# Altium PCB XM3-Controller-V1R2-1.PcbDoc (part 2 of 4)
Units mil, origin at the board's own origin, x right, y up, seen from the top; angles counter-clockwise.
Board outline 10629.92 x 4173.11 mil, 6 copper layers (TOP, GND1, LAYER3, PWR, GND2, BOTTOM), stack 62 mil thick; 362 components, 276 nets, 1145 pads, 503 vias.
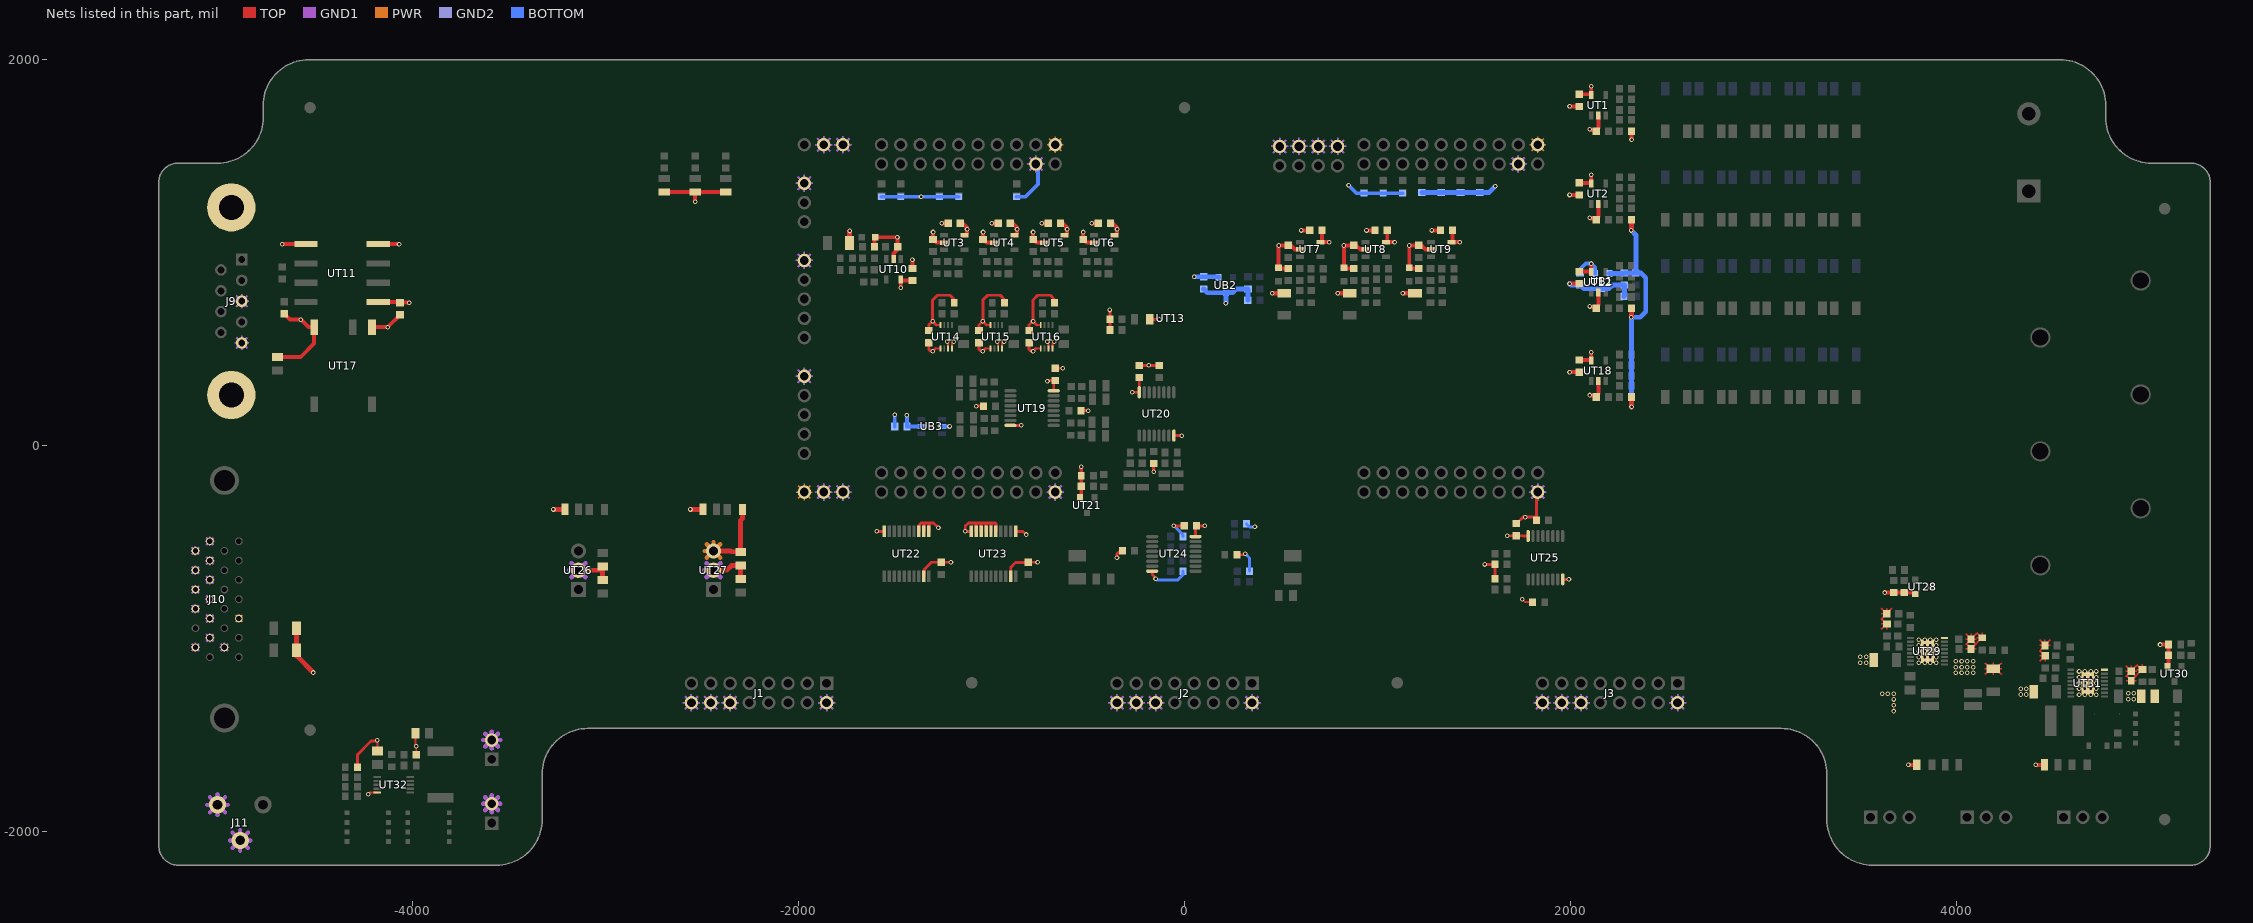
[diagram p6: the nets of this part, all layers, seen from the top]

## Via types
v1: diameter 24, hole 13, TOP to BOTTOM, 503 vias

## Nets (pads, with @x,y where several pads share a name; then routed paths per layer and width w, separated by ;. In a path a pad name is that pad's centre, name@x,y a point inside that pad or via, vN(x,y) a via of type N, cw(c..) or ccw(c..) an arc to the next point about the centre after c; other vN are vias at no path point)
0: CB1.2 CB2.2 CB3.2 CB4.2 CB5.2 CB6.2 CB7.2 CB8.2 CB9.2 CB10.2 CB11.2 CB12.2 CB13.2 CB14.2 CB15.2 CB16.2 CB17.2 CB18.2 CB19.2 CB20.2 CB21.2 CB22.2 CB23.2 CT1.2 CT3.1 CT4.2 CT6.1 CT7.2 CT8.2 CT9.2 CT10.2 CT11.2 CT12.2 CT13.2 CT14.2 CT15.1 CT16.1 CT17.1 CT18.1 CT19.2 CT20.2 CT21.2 CT22.2 CT30.2 CT31.2 CT32.2 CT33.2 CT35.2 CT38.1 CT39.2 CT43.1 CT44.2 CT45.2 CT46.2 CT48.2 CT49.2 CT50.2 CT54.1 CT59.2 CT60.2 CT61.2 CT62.2 CT63.2 CT64.2 CT65.2 CT66.2 CT67.2 CT68.2 CT69.2 CT70.2 CT71.2 CT72.2 CT73.1 CT74.1 CT75.2 CT76.2 CT77.2 CT78.2 CT79.1 CT80.1 CT81.2 CT83.2 CT84.2 CT85.2 CT86.2 CT87.2 CT88.2 DT1.2 DT2.2 DT3.2 DT4.2 DT5.2 DT8.1 DT12.2 J1.2 J1.12 J1.14 J1.16 J2.2 J2.12 J2.14 J2.16 J3.2 J3.12 J3.14 J3.16 J10.3 J10.4 J10.5 J10.9 J10.11 J10.13 J10.15 J10.17 J10.19 J10.21 J10.23 J10.25 J11.2 J11.3 J12.2 J13.2 RT4.1 RT36.2 RT37.1 RT51.1 RT53.1 RT55.1 RT72.2 RT73.2 RT74.2 RT82.1 RT89.2 RT101.2 RT107.2 RT111.1 RT114.1 RT117.2 RT123.2 RT124.2 RT126.1 RT131.2 RT134.1 RT137.1 RT140.2 UB1.3 UB2.3 UB3.2 UT1.2 UT2.2 UT3.2 UT4.2 UT5.2 UT6.2 UT7.2 UT8.2 UT9.2 UT10.2 UT11.4 UT12.2 UT13.20 UT13.22 UT13.60 UT13.62 UT13.82 UT13.84 UT13.86 UT13.88 UT13.93 UT13.98 UT13.101 UT13.103 UT13.104 UT13.106 UT13.107 UT14.1 UT14.4 UT15.1 UT15.4 UT16.1 UT16.4 UT17.1 UT18.2 UT19.8 UT20.8 UT21.2 UT22.1 UT22.2 UT22.3 UT22.10 UT22.19 UT23.1 UT23.5 UT23.6 UT23.7 UT23.8 UT23.9 UT23.10 UT23.19 UT24.8 UT25.8 UT26.2 UT27.2 UT28.2 UT29.16 UT29.17 UT30.2 UT31.16 UT31.17 UT32.5 | length 39476.6
  TOP w7: 3610.78,-870 CT71.2@3638.5,-870 ; 3611.23,-898.71 CT71.2@3638.5,-870 ; 3611.23,-841.29 CT71.2@3638.5,-870 ; 3611.29,-950.77 CT73.1@3640,-923.5 ; 3611.29,-923.5 CT73.1@3640,-923.5 ; 3611.29,-896.23 CT73.1@3640,-923.5 ; 3638.5,-841.29 CT71.2@3638.5,-870 ; 3640,-951.22 CT73.1@3640,-923.5 ; 3665.77,-841.29 CT71.2@3638.5,-870 ; 4047.78,-1003 CT74.1@4075.5,-1003 ; 4048.23,-1031.71 CT74.1@4075.5,-1003 ; 4048.23,-974.29 CT74.1@4075.5,-1003 ; 4048.76,-1053 RT126.1@4075.5,-1053 ; 4049.66,-1024.29 RT126.1@4075.5,-1053 ; 4075.5,-974.29 CT74.1@4075.5,-1003 ; 4101.34,-1024.29 RT126.1@4075.5,-1053 ; 4102.24,-1053 RT126.1@4075.5,-1053 ; 4102.77,-1031.71 CT74.1@4075.5,-1003 ; 4102.77,-974.29 CT74.1@4075.5,-1003 ; 4103.22,-1003 CT74.1@4075.5,-1003 ; 4105.29,-1020.34 RT123.2@4134,-994.5 ; 4105.29,-994.5 RT123.2@4134,-994.5 ; 4105.29,-968.66 RT123.2@4134,-994.5 ; 4134,-967.76 RT123.2@4134,-994.5 ; 4145.54,-1184.35 CT81.2@4190,-1155.94 ; 4145.54,-1155.94 CT81.2@4190,-1155.94 ; 4145.54,-1127.53 CT81.2@4190,-1155.94 ; 4190,-1187.6 CT81.2@4190,-1155.94 ; 4190,-1124.28 CT81.2@4190,-1155.94 ; 4234.46,-1184.35 CT81.2@4190,-1155.94 ; 4234.46,-1155.94 CT81.2@4190,-1155.94 ; 4234.46,-1127.53 CT81.2@4190,-1155.94 ; 4430.78,-1035 CT75.2@4458.5,-1035 ; 4431.23,-1063.71 CT75.2@4458.5,-1035 ; 4431.23,-1006.29 CT75.2@4458.5,-1035 ; 4431.29,-1115.77 CT79.1@4460,-1088.5 ; 4431.29,-1088.5 CT79.1@4460,-1088.5 ; 4431.29,-1061.23 CT79.1@4460,-1088.5 ; 4458.5,-1006.29 CT75.2@4458.5,-1035 ; 4460,-1116.22 CT79.1@4460,-1088.5 ; 4485.77,-1006.29 CT75.2@4458.5,-1035 ; 4486.22,-1035 CT75.2@4458.5,-1035 ; 4877.78,-1168 CT80.1@4905.5,-1168 ; 4878.23,-1196.71 CT80.1@4905.5,-1168 ; 4878.23,-1139.29 CT80.1@4905.5,-1168 ; 4878.76,-1218 RT134.1@4905.5,-1218 ; 4879.66,-1189.29 RT134.1@4905.5,-1218 ; 4905.5,-1139.29 CT80.1@4905.5,-1168 ; 4931.34,-1189.29 RT134.1@4905.5,-1218 ; 4932.24,-1218 RT134.1@4905.5,-1218 ; 4932.77,-1196.71 CT80.1@4905.5,-1168 ; 4932.77,-1139.29 CT80.1@4905.5,-1168 ; 4933.22,-1168 CT80.1@4905.5,-1168 ; 4935.29,-1185.34 RT131.2@4964,-1159.5 ; 4935.29,-1159.5 RT131.2@4964,-1159.5 ; 4935.29,-1133.66 RT131.2@4964,-1159.5 ; 4964,-1132.76 RT131.2@4964,-1159.5
  TOP w10: v1(-4230,-1805) -4221.67,-1796.67 UT32.5@-4182.5,-1796.67 ; CT88.2@-4182.5,-1581.24 v1(-4182.5,-1526.67) ; CT86.2@-3985.43,-1490 -3985.43,-1552.24 v1(-3981,-1556.67) CT87.2@-3981,-1601.67 ; -1291,504 UT14.1@-1265,504 ; UT14.4@-1205,504 -1205,530 v1(-1195,540) ; -1031,504 UT15.1@-1005,504 ; UT15.4@-945,504 -945,530 v1(-935,540) ; -771,504 UT16.1@-745,504 ; UT16.4@-685,504 -685,530 v1(-675,540)
  TOP w15: RT140.2@-4286,-1666.67 -4286,-1601 -4215,-1530 -4185.83,-1530 v1(-4182.5,-1526.67) ; v1(-1593.86,-443.86) UT22.10@-1555.16,-443.86 ; UT22.3@-1376.02,-443.86 -1376.02,-410.55 -1365.3,-399.83 -1350,-399.83 ; UT22.19@-1350.43,-676.14 -1350.43,-642.83 -1311.1,-603.5 CT65.2@-1260,-603.5 v1(-1210,-603.5) ; UT22.2@-1350.43,-443.86 -1350.43,-400.26 -1350,-399.83 ; CT44.2@-1325,533.5 -1325,500 -1315,490 v1(-1305,490) -1291,504 ; UT22.1@-1324.84,-443.86 -1324.84,-399.99 -1325,-399.83 ; v1(-1275,-425) -1300.17,-399.83 -1325,-399.83 ; UT23.10@-1105.16,-443.86 v1(-1136.14,-443.86) -1136.14,-415.94 -1120.03,-399.83 -1080,-399.83 ; UT23.9@-1079.57,-443.86 -1079.57,-400.26 -1080,-399.83 ; CT45.2@-1065,533.5 -1065,500 -1055,490 v1(-1045,490) -1031,504 ; UT23.8@-1053.98,-443.86 -1053.98,-400.85 -1055,-399.83 ; UT23.7@-1028.39,-443.86 -1028.39,-401.44 -1030,-399.83 ; UT23.6@-1002.8,-443.86 -1002.8,-402.03 -1005,-399.83 ; UT23.5@-977.2,-443.86 -977.2,-402.63 -980,-399.83 -1005,-399.83 ; UT19.8@-902.2,105.43 v1(-845,105.43) ; UT23.19@-900.43,-676.14 -900.43,-630.43 -875,-605 -811.5,-605 CT66.2@-810,-603.5 v1(-761.5,-603.5) ; UT23.1@-874.84,-443.86 -836.14,-443.86 v1(-820,-460) ; CT46.2@-805,533.5 -805,500 -795,490 v1(-785,490) -771,504 ; CT50.2@-670,401.5 v1(-630,401.5) ; RT101.2@-535.5,182 v1(-498.78,182) ; CT43.1@-386.5,600 RT82.1@-386.5,655 v1(-386.5,703.5) ; CT49.2@-235,416.5 -185.16,416.5 v1(-185,416.34) RT89.2@-130,416.34 ; UT24.8@-167.2,-649.57 -167.2,-667.8 -150,-685 v1(-150,-690) ; UT20.8@-55.43,52.8 v1(-15,52.8) ; v1(-55,-415) CT60.2@-1.5,-415 ; RT114.1@271.5,-565 310,-565 v1(315,-560) ; v1(1555,-615) CT64.2@1608.5,-615 CT67.2@1608.5,-690 ; CT61.2@1720,-403.5 1753.5,-370 v1(1765,-370) 1810.47,-370 RT111.1@1823.5,-383.03 ; RT111.1@1823.5,-385 RT111.1@1823.5,-383.03 ; UT13.20@1830,-240 1823.5,-246.5 RT111.1@1823.5,-383.03 ; UT25.8@1959.57,-692.2 v1(1992.2,-692.2) ; -1350,-399.83 -1325,-399.83 ; -1080,-399.83 -1055,-399.83 ; -1055,-399.83 -1030,-399.83 ; -1030,-399.83 -1005,-399.83
  TOP w20: UT17.1@-4210,615 v1(-4128.5,615) CT39.2@-4065,678.5 ; UT11.4@-4177.5,1045 v1(-4070,1045) ; DT1.2@-2695,1315 DT2.2@-2535.94,1315 ; v1(-2535.94,1265) DT2.2@-2535.94,1315 ; DT3.2@-2376.88,1315 DT2.2@-2535.94,1315 ; RT37.1@-1606,1030.64 -1606,1077.14 CT14.2@-1602.5,1080.64 v1(-1487.5,1080.64) -1487.5,1050.64 -1486.54,1049.68 -1486.54,1031.18 CT19.2@-1486,1030.64 -1486,1017.14 -1507.5,995.64 UT10.2@-1507.5,968.79 ; CT30.2@-1409.53,919.2 v1(-1409.53,963.61) ; v1(-1303.15,1107.4) CT15.1@-1303.15,1068.9 -1286.65,1052.4 UT3.2@-1246.3,1052.4 ; v1(-1258.15,1152.4) CT7.2@-1224.65,1152.4 ; v1(-1043.97,1107.4) CT16.1@-1043.97,1068.9 -1027.47,1052.4 UT4.2@-987.12,1052.4 ; v1(-998.97,1152.4) CT8.2@-965.47,1152.4 ; v1(-784.79,1107.4) CT17.1@-784.79,1068.9 -768.29,1052.4 UT5.2@-727.94,1052.4 ; v1(-739.79,1152.4) CT9.2@-706.29,1152.4 ; UT21.2@-541.29,-267.84 -534.79,-261.34 CT59.2@-534.79,-210.85 RT107.2@-534.79,-155.84 v1(-534.79,-109.34) ; v1(-525.61,1107.4) CT18.1@-525.61,1068.9 -509.11,1052.4 UT6.2@-468.76,1052.4 ; v1(-480.61,1152.4) CT10.2@-447.11,1152.4 ; RT51.1@537.5,919.19 491,919.19 CT31.2@487.5,922.69 v1(487.5,1037.69) 517.5,1037.69 518.46,1038.65 536.96,1038.65 CT20.2@537.5,1039.19 551,1039.19 572.5,1017.69 UT7.2@599.35,1017.69 ; v1(604.53,1115.66) CT11.2@648.94,1115.66 ; RT53.1@876.02,919.19 829.52,919.19 CT32.2@826.02,922.69 v1(826.02,1037.69) 856.02,1037.69 856.98,1038.65 875.48,1038.65 CT21.2@876.02,1039.19 889.52,1039.19 911.02,1017.69 UT8.2@937.87,1017.69 ; v1(943.05,1115.66) CT12.2@987.46,1115.66 ; RT55.1@1214.54,919.19 1168.04,919.19 CT33.2@1164.54,922.69 v1(1164.54,1037.69) 1194.54,1037.69 1195.5,1038.65 1214,1038.65 CT22.2@1214.54,1039.19 1228.04,1039.19 1249.54,1017.69 UT9.2@1276.39,1017.69 ; v1(1281.57,1115.66) CT13.2@1325.98,1115.66 ; v1(1995,381.32) CT48.2@2045,381.32 ; v1(1995,840.38) CT35.2@2045,840.38 ; v1(1995,1299.44) CT4.2@2045,1299.44 ; v1(1995,1758.5) CT1.2@2045,1758.5 ; v1(2100,262.82) 2103.5,259.32 2132,259.32 CT54.1@2133.5,257.82 ; v1(2100,721.88) 2103.5,718.38 2132,718.38 CT38.1@2133.5,716.88 ; v1(2100,1180.94) 2103.5,1177.44 2132,1177.44 CT6.1@2133.5,1175.94 ; v1(2100,1640) 2103.5,1636.5 2132,1636.5 CT3.1@2133.5,1635 ; CT54.1@2133.5,252.82 CT54.1@2133.5,257.82 ; CT38.1@2133.5,711.88 CT38.1@2133.5,716.88 ; CT6.1@2133.5,1170.94 CT6.1@2133.5,1175.94 ; CT3.1@2133.5,1630 CT3.1@2133.5,1635 ; UT18.2@2145,334.67 2145,269.32 CT54.1@2133.5,257.82 ; UT12.2@2145,793.73 2145,728.38 CT38.1@2133.5,716.88 ; UT2.2@2145,1252.79 2145,1187.44 CT6.1@2133.5,1175.94 ; UT1.2@2145,1711.85 2145,1646.5 CT3.1@2133.5,1635 ; v1(2316.5,1586.5) RT4.1@2316.5,1630 ; v1(3628.5,-760.5) RT117.2@3675,-760.5 CT69.2@3730.01,-760.5 3780.5,-760.5 UT28.2@3787,-767 ; v1(3751.53,-1653.47) RT137.1@3794.85,-1653.47 ; v1(4411.53,-1653.47) DT12.2@4456,-1653.47 ; v1(5055,-1030) RT124.2@5099.5,-1030 CT77.2@5099.5,-1085.01 5099.5,-1135.5 UT30.2@5093,-1142
  TOP w25: CT72.2@-4600.94,-945 CT76.2@-4600.94,-1060 -4600.94,-1089.06 v1(-4515,-1175) ; v1(-3270,-330) DT4.2@-3210,-330 ; UT26.2@-3140.47,-645 -3034.57,-645 CT63.2@-3015,-625.43 CT70.2@-3015,-694.57 ; v1(-2560,-330) DT5.2@-2495,-330 ; UT27.2@-2440.47,-645 -2371.63,-645 -2347.06,-620.43 CT62.2@-2300,-620.43 CT68.2@-2300,-689.57 ; RT36.2@-1735.41,1050.64 -1735.19,1050.86 v1(-1735.19,1113.14) ; v1(455,790) 517.28,790 RT72.2@517.5,789.78 ; v1(793.52,790) 855.8,790 RT73.2@856.02,789.78 ; v1(1132.04,790) 1194.32,790 RT74.2@1194.54,789.78
  GND1 w7: -5148.02,-1045 J10.3@-5125,-1045 ; -5148.02,-845 J10.11@-5125,-845 ; -5148.02,-745 J10.15@-5125,-745 ; -5148.02,-645 J10.19@-5125,-645 ; -5148.02,-545 J10.23@-5125,-545 ; -5143.28,-1063.28 J10.3@-5125,-1045 ; -5143.28,-1026.72 J10.3@-5125,-1045 ; -5143.28,-863.28 J10.11@-5125,-845 ; -5143.28,-826.72 J10.11@-5125,-845 ; -5143.28,-763.28 J10.15@-5125,-745 ; -5143.28,-726.72 J10.15@-5125,-745 ; -5143.28,-663.28 J10.19@-5125,-645 ; -5143.28,-626.72 J10.19@-5125,-645 ; -5143.28,-563.28 J10.23@-5125,-545 ; -5143.28,-526.72 J10.23@-5125,-545 ; -5125,-1068.02 J10.3@-5125,-1045 ; -5125,-1021.98 J10.3@-5125,-1045 ; -5125,-868.02 J10.11@-5125,-845 ; -5125,-821.98 J10.11@-5125,-845 ; -5125,-768.02 J10.15@-5125,-745 ; -5125,-721.98 J10.15@-5125,-745 ; -5125,-668.02 J10.19@-5125,-645 ; -5125,-621.98 J10.19@-5125,-645 ; -5125,-568.02 J10.23@-5125,-545 ; -5125,-521.98 J10.23@-5125,-545 ; -5106.72,-1063.28 J10.3@-5125,-1045 ; -5106.72,-1026.72 J10.3@-5125,-1045 ; -5106.72,-863.28 J10.11@-5125,-845 ; -5106.72,-826.72 J10.11@-5125,-845 ; -5106.72,-763.28 J10.15@-5125,-745 ; -5106.72,-726.72 J10.15@-5125,-745 ; -5106.72,-663.28 J10.19@-5125,-645 ; -5106.72,-626.72 J10.19@-5125,-645 ; -5106.72,-563.28 J10.23@-5125,-545 ; -5106.72,-526.72 J10.23@-5125,-545 ; -5101.98,-1045 J10.3@-5125,-1045 ; -5101.98,-845 J10.11@-5125,-845 ; -5101.98,-745 J10.15@-5125,-745 ; -5101.98,-645 J10.19@-5125,-645 ; -5101.98,-545 J10.23@-5125,-545 ; -5073.02,-995 J10.5@-5050,-995 ; -5073.02,-895 J10.9@-5050,-895 ; -5073.02,-795 J10.13@-5050,-795 ; -5073.02,-695 J10.17@-5050,-695 ; -5073.02,-595 J10.21@-5050,-595 ; -5073.02,-495 J10.25@-5050,-495 ; -5068.28,-1013.28 J10.5@-5050,-995 ; -5068.28,-976.72 J10.5@-5050,-995 ; -5068.28,-913.28 J10.9@-5050,-895 ; -5068.28,-876.72 J10.9@-5050,-895 ; -5068.28,-813.28 J10.13@-5050,-795 ; -5068.28,-776.72 J10.13@-5050,-795 ; -5068.28,-713.28 J10.17@-5050,-695 ; -5068.28,-676.72 J10.17@-5050,-695 ; -5068.28,-613.28 J10.21@-5050,-595 ; -5068.28,-576.72 J10.21@-5050,-595 ; -5068.28,-513.28 J10.25@-5050,-495 ; -5068.28,-476.72 J10.25@-5050,-495 ; -5050,-1018.02 J10.5@-5050,-995 ; -5050,-971.98 J10.5@-5050,-995 ; -5050,-918.02 J10.9@-5050,-895 ; -5050,-871.98 J10.9@-5050,-895 ; -5050,-818.02 J10.13@-5050,-795 ; -5050,-771.98 J10.13@-5050,-795 ; -5050,-718.02 J10.17@-5050,-695 ; -5050,-671.98 J10.17@-5050,-695 ; -5050,-618.02 J10.21@-5050,-595 ; -5050,-571.98 J10.21@-5050,-595 ; -5050,-518.02 J10.25@-5050,-495 ; -5050,-471.98 J10.25@-5050,-495 ; -5031.72,-1013.28 J10.5@-5050,-995 ; -5031.72,-976.72 J10.5@-5050,-995 ; -5031.72,-913.28 J10.9@-5050,-895 ; -5031.72,-876.72 J10.9@-5050,-895 ; -5031.72,-813.28 J10.13@-5050,-795 ; -5031.72,-776.72 J10.13@-5050,-795 ; -5031.72,-713.28 J10.17@-5050,-695 ; -5031.72,-676.72 J10.17@-5050,-695 ; -5031.72,-613.28 J10.21@-5050,-595 ; -5031.72,-576.72 J10.21@-5050,-595 ; -5031.72,-513.28 J10.25@-5050,-495 ; -5031.72,-476.72 J10.25@-5050,-495 ; -5026.98,-995 J10.5@-5050,-995 ; -5026.98,-895 J10.9@-5050,-895 ; -5026.98,-795 J10.13@-5050,-795 ; -5026.98,-695 J10.17@-5050,-695 ; -5026.98,-595 J10.21@-5050,-595 ; -5026.98,-495 J10.25@-5050,-495 ; -4998.02,-1045 J10.4@-4975,-1045 ; -4993.28,-1063.28 J10.4@-4975,-1045 ; -4993.28,-1026.72 J10.4@-4975,-1045 ; -4975,-1068.02 J10.4@-4975,-1045 ; -4975,-1021.98 J10.4@-4975,-1045 ; -4956.72,-1063.28 J10.4@-4975,-1045 ; -4956.72,-1026.72 J10.4@-4975,-1045 ; -4951.98,-1045 J10.4@-4975,-1045 ; -2598.74,-1331.36 J1.16@-2554.72,-1331.36 ; -2587.85,-1364.49 J1.16@-2554.72,-1331.36 ; -2587.85,-1298.23 J1.16@-2554.72,-1331.36 ; -2554.72,-1375.38 J1.16@-2554.72,-1331.36 ; -2554.72,-1287.34 J1.16@-2554.72,-1331.36 ; -2521.59,-1364.49 J1.16@-2554.72,-1331.36 ; -2521.59,-1298.23 J1.16@-2554.72,-1331.36 ; -2510.7,-1331.36 J1.16@-2554.72,-1331.36 ; -2498.74,-1331.36 J1.14@-2454.72,-1331.36 ; -2487.85,-1364.49 J1.14@-2454.72,-1331.36 ; -2487.85,-1298.23 J1.14@-2454.72,-1331.36 ; -2454.72,-1375.38 J1.14@-2454.72,-1331.36 ; -2454.72,-1287.34 J1.14@-2454.72,-1331.36 ; -2421.59,-1364.49 J1.14@-2454.72,-1331.36 ; -2421.59,-1298.23 J1.14@-2454.72,-1331.36 ; -2410.7,-1331.36 J1.14@-2454.72,-1331.36 ; -2398.74,-1331.36 J1.12@-2354.72,-1331.36 ; -2387.85,-1364.49 J1.12@-2354.72,-1331.36 ; -2387.85,-1298.23 J1.12@-2354.72,-1331.36 ; -2354.72,-1375.38 J1.12@-2354.72,-1331.36 ; -2354.72,-1287.34 J1.12@-2354.72,-1331.36 ; -2321.59,-1364.49 J1.12@-2354.72,-1331.36 ; -2321.59,-1298.23 J1.12@-2354.72,-1331.36 ; -2310.7,-1331.36 J1.12@-2354.72,-1331.36 ; -2014.02,360 UT13.93@-1970,360 ; -2014.02,960 UT13.98@-1970,960 ; -2014.02,1360 UT13.101@-1970,1360 ; -2003.13,326.87 UT13.93@-1970,360 ; -2003.13,393.13 UT13.93@-1970,360 ; -2003.13,926.87 UT13.98@-1970,960 ; -2003.13,993.13 UT13.98@-1970,960 ; -2003.13,1326.87 UT13.101@-1970,1360 ; -2003.13,1393.13 UT13.101@-1970,1360 ; -1970,315.98 UT13.93@-1970,360 ; -1970,404.02 UT13.93@-1970,360 ; -1970,915.98 UT13.98@-1970,960 ; -1970,1004.02 UT13.98@-1970,960 ; -1970,1315.98 UT13.101@-1970,1360 ; -1970,1404.02 UT13.101@-1970,1360 ; -1936.87,326.87 UT13.93@-1970,360 ; -1936.87,393.13 UT13.93@-1970,360 ; -1936.87,926.87 UT13.98@-1970,960 ; -1936.87,993.13 UT13.98@-1970,960 ; -1936.87,1326.87 UT13.101@-1970,1360 ; -1936.87,1393.13 UT13.101@-1970,1360 ; -1925.98,360 UT13.93@-1970,360 ; -1925.98,960 UT13.98@-1970,960 ; -1925.98,1360 UT13.101@-1970,1360 ; -1914.02,-240 UT13.103@-1870,-240 ; -1914.02,1560 UT13.106@-1870,1560 ; -1903.13,-273.13 UT13.103@-1870,-240 ; -1903.13,-206.87 UT13.103@-1870,-240 ; -1903.13,1526.87 UT13.106@-1870,1560 ; -1903.13,1593.13 UT13.106@-1870,1560 ; -1898.74,-1331.36 J1.2@-1854.72,-1331.36 ; -1887.85,-1364.49 J1.2@-1854.72,-1331.36 ; -1887.85,-1298.23 J1.2@-1854.72,-1331.36 ; -1870,-284.02 UT13.103@-1870,-240 ; -1870,-195.98 UT13.103@-1870,-240 ; -1870,1515.98 UT13.106@-1870,1560 ; -1870,1604.02 UT13.106@-1870,1560 ; -1854.72,-1375.38 J1.2@-1854.72,-1331.36 ; -1854.72,-1287.34 J1.2@-1854.72,-1331.36 ; -1836.87,-273.13 UT13.103@-1870,-240 ; -1836.87,-206.87 UT13.103@-1870,-240 ; -1836.87,1526.87 UT13.106@-1870,1560 ; -1836.87,1593.13 UT13.106@-1870,1560 ; -1825.98,-240 UT13.103@-1870,-240 ; -1825.98,1560 UT13.106@-1870,1560 ; -1821.59,-1364.49 J1.2@-1854.72,-1331.36 ; -1821.59,-1298.23 J1.2@-1854.72,-1331.36 ; -1814.02,-240 UT13.104@-1770,-240 ; -1814.02,1560 UT13.107@-1770,1560 ; -1810.7,-1331.36 J1.2@-1854.72,-1331.36 ; -1803.13,-273.13 UT13.104@-1770,-240 ; -1803.13,-206.87 UT13.104@-1770,-240 ; -1803.13,1526.87 UT13.107@-1770,1560 ; -1803.13,1593.13 UT13.107@-1770,1560 ; -1770,-284.02 UT13.104@-1770,-240 ; -1770,-195.98 UT13.104@-1770,-240 ; -1770,1515.98 UT13.107@-1770,1560 ; -1770,1604.02 UT13.107@-1770,1560 ; -1736.87,-273.13 UT13.104@-1770,-240 ; -1736.87,-206.87 UT13.104@-1770,-240 ; -1736.87,1526.87 UT13.107@-1770,1560 ; -1736.87,1593.13 UT13.107@-1770,1560 ; -1725.98,-240 UT13.104@-1770,-240 ; -1725.98,1560 UT13.107@-1770,1560 ; -814.02,1460 UT13.62@-770,1460 ; -803.13,1426.87 UT13.62@-770,1460 ; -803.13,1493.13 UT13.62@-770,1460 ; -770,1415.98 UT13.62@-770,1460 ; -770,1504.02 UT13.62@-770,1460 ; -736.87,1426.87 UT13.62@-770,1460 ; -736.87,1493.13 UT13.62@-770,1460 ; -725.98,1460 UT13.62@-770,1460 ; -714.02,-240 UT13.60@-670,-240 ; -703.13,-273.13 UT13.60@-670,-240 ; -703.13,-206.87 UT13.60@-670,-240 ; -670,-284.02 UT13.60@-670,-240 ; -670,-195.98 UT13.60@-670,-240 ; -636.87,-273.13 UT13.60@-670,-240 ; -636.87,-206.87 UT13.60@-670,-240 ; -625.98,-240 UT13.60@-670,-240 ; -394.02,-1331.36 J2.16@-350,-1331.36 ; -383.13,-1364.49 J2.16@-350,-1331.36 ; -383.13,-1298.23 J2.16@-350,-1331.36 ; -350,-1375.38 J2.16@-350,-1331.36 ; -350,-1287.34 J2.16@-350,-1331.36 ; -316.87,-1364.49 J2.16@-350,-1331.36 ; -316.87,-1298.23 J2.16@-350,-1331.36 ; -305.98,-1331.36 J2.16@-350,-1331.36 ; -294.02,-1331.36 J2.14@-250,-1331.36 ; -283.13,-1364.49 J2.14@-250,-1331.36 ; -283.13,-1298.23 J2.14@-250,-1331.36 ; -250,-1375.38 J2.14@-250,-1331.36 ; -250,-1287.34 J2.14@-250,-1331.36 ; -216.87,-1364.49 J2.14@-250,-1331.36 ; -216.87,-1298.23 J2.14@-250,-1331.36 ; -205.98,-1331.36 J2.14@-250,-1331.36 ; -194.02,-1331.36 J2.12@-150,-1331.36 ; -183.13,-1364.49 J2.12@-150,-1331.36 ; -183.13,-1298.23 J2.12@-150,-1331.36 ; -150,-1375.38 J2.12@-150,-1331.36 ; -150,-1287.34 J2.12@-150,-1331.36 ; -116.87,-1364.49 J2.12@-150,-1331.36 ; -116.87,-1298.23 J2.12@-150,-1331.36 ; -105.98,-1331.36 J2.12@-150,-1331.36 ; 305.98,-1331.36 J2.2@350,-1331.36 ; 316.87,-1364.49 J2.2@350,-1331.36 ; 316.87,-1298.23 J2.2@350,-1331.36 ; 350,-1375.38 J2.2@350,-1331.36 ; 350,-1287.34 J2.2@350,-1331.36 ; 383.13,-1364.49 J2.2@350,-1331.36 ; 383.13,-1298.23 J2.2@350,-1331.36 ; 394.02,-1331.36 J2.2@350,-1331.36 ; 448.81,1550.79 UT13.88@492.83,1550.79 ; 459.7,1517.66 UT13.88@492.83,1550.79 ; 459.7,1583.92 UT13.88@492.83,1550.79 ; 492.83,1506.77 UT13.88@492.83,1550.79 ; 492.83,1594.81 UT13.88@492.83,1550.79 ; 525.96,1517.66 UT13.88@492.83,1550.79 ; 525.96,1583.92 UT13.88@492.83,1550.79 ; 536.85,1550.79 UT13.88@492.83,1550.79 ; 548.81,1550.79 UT13.86@592.83,1550.79 ; 559.7,1517.66 UT13.86@592.83,1550.79 ; 559.7,1583.92 UT13.86@592.83,1550.79 ; 592.83,1506.77 UT13.86@592.83,1550.79 ; 592.83,1594.81 UT13.86@592.83,1550.79 ; 625.96,1517.66 UT13.86@592.83,1550.79 ; 625.96,1583.92 UT13.86@592.83,1550.79 ; 636.85,1550.79 UT13.86@592.83,1550.79 ; 648.81,1550.79 UT13.84@692.83,1550.79 ; 659.7,1517.66 UT13.84@692.83,1550.79 ; 659.7,1583.92 UT13.84@692.83,1550.79 ; 692.83,1506.77 UT13.84@692.83,1550.79 ; 692.83,1594.81 UT13.84@692.83,1550.79 ; 725.96,1517.66 UT13.84@692.83,1550.79 ; 725.96,1583.92 UT13.84@692.83,1550.79 ; 736.85,1550.79 UT13.84@692.83,1550.79 ; 748.81,1550.79 UT13.82@792.83,1550.79 ; 759.7,1517.66 UT13.82@792.83,1550.79 ; 759.7,1583.92 UT13.82@792.83,1550.79 ; 792.83,1506.77 UT13.82@792.83,1550.79 ; 792.83,1594.81 UT13.82@792.83,1550.79 ; 825.96,1517.66 UT13.82@792.83,1550.79 ; 825.96,1583.92 UT13.82@792.83,1550.79 ; 836.85,1550.79 UT13.82@792.83,1550.79 ; 1685.98,1460 UT13.22@1730,1460 ; 1696.87,1426.87 UT13.22@1730,1460 ; 1696.87,1493.13 UT13.22@1730,1460 ; 1730,1415.98 UT13.22@1730,1460 ; 1730,1504.02 UT13.22@1730,1460 ; 1763.13,1426.87 UT13.22@1730,1460 ; 1763.13,1493.13 UT13.22@1730,1460 ; 1774.02,1460 UT13.22@1730,1460 ; 1785.98,-240 UT13.20@1830,-240 ; 1796.87,-273.13 UT13.20@1830,-240 ; 1796.87,-206.87 UT13.20@1830,-240 ; 1810.7,-1331.36 J3.16@1854.72,-1331.36 ; 1821.59,-1364.49 J3.16@1854.72,-1331.36 ; 1821.59,-1298.23 J3.16@1854.72,-1331.36 ; 1830,-284.02 UT13.20@1830,-240 ; 1830,-195.98 UT13.20@1830,-240 ; 1854.72,-1375.38 J3.16@1854.72,-1331.36 ; 1854.72,-1287.34 J3.16@1854.72,-1331.36 ; 1863.13,-273.13 UT13.20@1830,-240 ; 1863.13,-206.87 UT13.20@1830,-240 ; 1874.02,-240 UT13.20@1830,-240 ; 1887.85,-1364.49 J3.16@1854.72,-1331.36 ; 1887.85,-1298.23 J3.16@1854.72,-1331.36 ; 1898.74,-1331.36 J3.16@1854.72,-1331.36 ; 1910.7,-1331.36 J3.14@1954.72,-1331.36 ; 1921.59,-1364.49 J3.14@1954.72,-1331.36 ; 1921.59,-1298.23 J3.14@1954.72,-1331.36 ; 1954.72,-1375.38 J3.14@1954.72,-1331.36 ; 1954.72,-1287.34 J3.14@1954.72,-1331.36 ; 1987.85,-1364.49 J3.14@1954.72,-1331.36 ; 1987.85,-1298.23 J3.14@1954.72,-1331.36 ; 1998.74,-1331.36 J3.14@1954.72,-1331.36 ; 2010.7,-1331.36 J3.12@2054.72,-1331.36 ; 2021.59,-1364.49 J3.12@2054.72,-1331.36 ; 2021.59,-1298.23 J3.12@2054.72,-1331.36 ; 2054.72,-1375.38 J3.12@2054.72,-1331.36 ; 2054.72,-1287.34 J3.12@2054.72,-1331.36 ; 2087.85,-1364.49 J3.12@2054.72,-1331.36 ; 2087.85,-1298.23 J3.12@2054.72,-1331.36 ; 2098.74,-1331.36 J3.12@2054.72,-1331.36 ; 2510.7,-1331.36 J3.2@2554.72,-1331.36 ; 2521.59,-1364.49 J3.2@2554.72,-1331.36 ; 2521.59,-1298.23 J3.2@2554.72,-1331.36 ; 2554.72,-1375.38 J3.2@2554.72,-1331.36 ; 2554.72,-1287.34 J3.2@2554.72,-1331.36 ; 2587.85,-1364.49 J3.2@2554.72,-1331.36 ; 2587.85,-1298.23 J3.2@2554.72,-1331.36 ; 2598.74,-1331.36 J3.2@2554.72,-1331.36
  GND1 w20: -5065.02,-1860 J11.2@-5011,-1860 ; -5051.2,-1900.2 J11.2@-5011,-1860 ; -5051.2,-1819.8 J11.2@-5011,-1860 ; -5011,-1914.02 J11.2@-5011,-1860 ; -5011,-1805.98 J11.2@-5011,-1860 ; -4970.8,-1900.2 J11.2@-5011,-1860 ; -4970.8,-1819.8 J11.2@-5011,-1860 ; -4956.98,-1860 J11.2@-5011,-1860 ; -4947.02,-2045 J11.3@-4893,-2045 ; -4933.2,-2085.2 J11.3@-4893,-2045 ; -4933.2,-2004.8 J11.3@-4893,-2045 ; -4893,-2099.02 J11.3@-4893,-2045 ; -4893,-1990.98 J11.3@-4893,-2045 ; -4852.8,-2085.2 J11.3@-4893,-2045 ; -4852.8,-2004.8 J11.3@-4893,-2045 ; -4838.98,-2045 J11.3@-4893,-2045
  GND1 w22: -3634.02,-1855 J12.2@-3590,-1855 ; -3634.02,-1525 J13.2@-3590,-1525 ; -3623.13,-1888.13 J12.2@-3590,-1855 ; -3623.13,-1821.87 J12.2@-3590,-1855 ; -3623.13,-1558.13 J13.2@-3590,-1525 ; -3623.13,-1491.87 J13.2@-3590,-1525 ; -3590,-1899.02 J12.2@-3590,-1855 ; -3590,-1810.98 J12.2@-3590,-1855 ; -3590,-1569.02 J13.2@-3590,-1525 ; -3590,-1480.98 J13.2@-3590,-1525 ; -3556.87,-1888.13 J12.2@-3590,-1855 ; -3556.87,-1821.87 J12.2@-3590,-1855 ; -3556.87,-1558.13 J13.2@-3590,-1525 ; -3556.87,-1491.87 J13.2@-3590,-1525 ; -3545.98,-1855 J12.2@-3590,-1855 ; -3545.98,-1525 J13.2@-3590,-1525 ; -3188.86,-645 UT26.2@-3140.47,-645 ; -3176.69,-681.22 UT26.2@-3140.47,-645 ; -3176.69,-608.78 UT26.2@-3140.47,-645 ; -3104.25,-681.22 UT26.2@-3140.47,-645 ; -3104.25,-608.78 UT26.2@-3140.47,-645 ; -3092.08,-645 UT26.2@-3140.47,-645 ; -2488.86,-645 UT27.2@-2440.47,-645 ; -2476.69,-681.22 UT27.2@-2440.47,-645 ; -2476.69,-608.78 UT27.2@-2440.47,-645 ; -2404.25,-681.22 UT27.2@-2440.47,-645 ; -2404.25,-608.78 UT27.2@-2440.47,-645 ; -2392.08,-645 UT27.2@-2440.47,-645
  GND2 w7: -5141.86,-1061.86 J10.3@-5125,-1045 ; -5141.86,-1028.14 J10.3@-5125,-1045 ; -5141.86,-861.86 J10.11@-5125,-845 ; -5141.86,-828.14 J10.11@-5125,-845 ; -5141.86,-761.86 J10.15@-5125,-745 ; -5141.86,-728.14 J10.15@-5125,-745 ; -5141.86,-661.86 J10.19@-5125,-645 ; -5141.86,-628.14 J10.19@-5125,-645 ; -5141.86,-561.86 J10.23@-5125,-545 ; -5141.86,-528.14 J10.23@-5125,-545 ; -5108.14,-1061.86 J10.3@-5125,-1045 ; -5108.14,-1028.14 J10.3@-5125,-1045 ; -5108.14,-861.86 J10.11@-5125,-845 ; -5108.14,-828.14 J10.11@-5125,-845 ; -5108.14,-761.86 J10.15@-5125,-745 ; -5108.14,-728.14 J10.15@-5125,-745 ; -5108.14,-661.86 J10.19@-5125,-645 ; -5108.14,-628.14 J10.19@-5125,-645 ; -5108.14,-561.86 J10.23@-5125,-545 ; -5108.14,-528.14 J10.23@-5125,-545 ; -5066.86,-1011.86 J10.5@-5050,-995 ; -5066.86,-978.14 J10.5@-5050,-995 ; -5066.86,-911.86 J10.9@-5050,-895 ; -5066.86,-878.14 J10.9@-5050,-895 ; -5066.86,-811.86 J10.13@-5050,-795 ; -5066.86,-778.14 J10.13@-5050,-795 ; -5066.86,-711.86 J10.17@-5050,-695 ; -5066.86,-678.14 J10.17@-5050,-695 ; -5066.86,-611.86 J10.21@-5050,-595 ; -5066.86,-578.14 J10.21@-5050,-595 ; -5066.86,-511.86 J10.25@-5050,-495 ; -5066.86,-478.14 J10.25@-5050,-495 ; -5033.14,-1011.86 J10.5@-5050,-995 ; -5033.14,-978.14 J10.5@-5050,-995 ; -5033.14,-911.86 J10.9@-5050,-895 ; -5033.14,-878.14 J10.9@-5050,-895 ; -5033.14,-811.86 J10.13@-5050,-795 ; -5033.14,-778.14 J10.13@-5050,-795 ; -5033.14,-711.86 J10.17@-5050,-695 ; -5033.14,-678.14 J10.17@-5050,-695 ; -5033.14,-611.86 J10.21@-5050,-595 ; -5033.14,-578.14 J10.21@-5050,-595 ; -5033.14,-511.86 J10.25@-5050,-495 ; -5033.14,-478.14 J10.25@-5050,-495 ; -4991.86,-1061.86 J10.4@-4975,-1045 ; -4991.86,-1028.14 J10.4@-4975,-1045 ; -4958.14,-1061.86 J10.4@-4975,-1045 ; -4958.14,-1028.14 J10.4@-4975,-1045 ; -2596.74,-1331.36 J1.16@-2554.72,-1331.36 ; -2586.43,-1363.07 J1.16@-2554.72,-1331.36 ; -2586.43,-1299.65 J1.16@-2554.72,-1331.36 ; -2554.72,-1373.38 J1.16@-2554.72,-1331.36 ; -2554.72,-1289.34 J1.16@-2554.72,-1331.36 ; -2523.01,-1363.07 J1.16@-2554.72,-1331.36 ; -2523.01,-1299.65 J1.16@-2554.72,-1331.36 ; -2512.7,-1331.36 J1.16@-2554.72,-1331.36 ; -2496.74,-1331.36 J1.14@-2454.72,-1331.36 ; -2486.43,-1363.07 J1.14@-2454.72,-1331.36 ; -2486.43,-1299.65 J1.14@-2454.72,-1331.36 ; -2454.72,-1373.38 J1.14@-2454.72,-1331.36 ; -2454.72,-1289.34 J1.14@-2454.72,-1331.36 ; -2423.01,-1363.07 J1.14@-2454.72,-1331.36 ; -2423.01,-1299.65 J1.14@-2454.72,-1331.36 ; -2412.7,-1331.36 J1.14@-2454.72,-1331.36 ; -2396.74,-1331.36 J1.12@-2354.72,-1331.36 ; -2386.43,-1363.07 J1.12@-2354.72,-1331.36 ; -2386.43,-1299.65 J1.12@-2354.72,-1331.36 ; -2354.72,-1373.38 J1.12@-2354.72,-1331.36 ; -2354.72,-1289.34 J1.12@-2354.72,-1331.36 ; -2323.01,-1363.07 J1.12@-2354.72,-1331.36 ; -2323.01,-1299.65 J1.12@-2354.72,-1331.36 ; -2312.7,-1331.36 J1.12@-2354.72,-1331.36 ; -2012.02,360 UT13.93@-1970,360 ; -2012.02,960 UT13.98@-1970,960 ; -2012.02,1360 UT13.101@-1970,1360 ; -2001.71,328.29 UT13.93@-1970,360 ; -2001.71,391.71 UT13.93@-1970,360 ; -2001.71,928.29 UT13.98@-1970,960 ; -2001.71,991.71 UT13.98@-1970,960 ; -2001.71,1328.29 UT13.101@-1970,1360 ; -2001.71,1391.71 UT13.101@-1970,1360 ; -1970,317.98 UT13.93@-1970,360 ; -1970,402.02 UT13.93@-1970,360 ; -1970,917.98 UT13.98@-1970,960 ; -1970,1002.02 UT13.98@-1970,960 ; -1970,1317.98 UT13.101@-1970,1360 ; -1970,1402.02 UT13.101@-1970,1360 ; -1938.29,328.29 UT13.93@-1970,360 ; -1938.29,391.71 UT13.93@-1970,360 ; -1938.29,928.29 UT13.98@-1970,960 ; -1938.29,991.71 UT13.98@-1970,960 ; -1938.29,1328.29 UT13.101@-1970,1360 ; -1938.29,1391.71 UT13.101@-1970,1360 ; -1927.98,360 UT13.93@-1970,360 ; -1927.98,960 UT13.98@-1970,960 ; -1927.98,1360 UT13.101@-1970,1360 ; -1912.02,-240 UT13.103@-1870,-240 ; -1912.02,1560 UT13.106@-1870,1560 ; -1901.71,-271.71 UT13.103@-1870,-240 ; -1901.71,-208.29 UT13.103@-1870,-240 ; -1901.71,1528.29 UT13.106@-1870,1560 ; -1901.71,1591.71 UT13.106@-1870,1560 ; -1896.74,-1331.36 J1.2@-1854.72,-1331.36 ; -1886.43,-1363.07 J1.2@-1854.72,-1331.36 ; -1886.43,-1299.65 J1.2@-1854.72,-1331.36 ; -1870,-282.02 UT13.103@-1870,-240 ; -1870,-197.98 UT13.103@-1870,-240 ; -1870,1517.98 UT13.106@-1870,1560 ; -1870,1602.02 UT13.106@-1870,1560 ; -1854.72,-1373.38 J1.2@-1854.72,-1331.36 ; -1854.72,-1289.34 J1.2@-1854.72,-1331.36 ; -1838.29,-271.71 UT13.103@-1870,-240 ; -1838.29,-208.29 UT13.103@-1870,-240 ; -1838.29,1528.29 UT13.106@-1870,1560 ; -1838.29,1591.71 UT13.106@-1870,1560 ; -1827.98,-240 UT13.103@-1870,-240 ; -1827.98,1560 UT13.106@-1870,1560 ; -1823.01,-1363.07 J1.2@-1854.72,-1331.36 ; -1823.01,-1299.65 J1.2@-1854.72,-1331.36 ; -1812.7,-1331.36 J1.2@-1854.72,-1331.36 ; -1812.02,-240 UT13.104@-1770,-240 ; -1812.02,1560 UT13.107@-1770,1560 ; -1801.71,-271.71 UT13.104@-1770,-240 ; -1801.71,-208.29 UT13.104@-1770,-240 ; -1801.71,1528.29 UT13.107@-1770,1560 ; -1801.71,1591.71 UT13.107@-1770,1560 ; -1770,-282.02 UT13.104@-1770,-240 ; -1770,-197.98 UT13.104@-1770,-240 ; -1770,1517.98 UT13.107@-1770,1560 ; -1770,1602.02 UT13.107@-1770,1560 ; -1738.29,-271.71 UT13.104@-1770,-240 ; -1738.29,-208.29 UT13.104@-1770,-240 ; -1738.29,1528.29 UT13.107@-1770,1560 ; -1738.29,1591.71 UT13.107@-1770,1560 ; -1727.98,-240 UT13.104@-1770,-240 ; -1727.98,1560 UT13.107@-1770,1560 ; -812.02,1460 UT13.62@-770,1460 ; -801.71,1428.29 UT13.62@-770,1460 ; -801.71,1491.71 UT13.62@-770,1460 ; -770,1417.98 UT13.62@-770,1460 ; -770,1502.02 UT13.62@-770,1460 ; -738.29,1428.29 UT13.62@-770,1460 ; -738.29,1491.71 UT13.62@-770,1460 ; -727.98,1460 UT13.62@-770,1460 ; -712.02,-240 UT13.60@-670,-240 ; -701.71,-271.71 UT13.60@-670,-240 ; -701.71,-208.29 UT13.60@-670,-240 ; -670,-282.02 UT13.60@-670,-240 ; -670,-197.98 UT13.60@-670,-240 ; -638.29,-271.71 UT13.60@-670,-240 ; -638.29,-208.29 UT13.60@-670,-240 ; -627.98,-240 UT13.60@-670,-240 ; -392.02,-1331.36 J2.16@-350,-1331.36 ; -381.71,-1363.07 J2.16@-350,-1331.36 ; -381.71,-1299.65 J2.16@-350,-1331.36 ; -350,-1373.38 J2.16@-350,-1331.36 ; -350,-1289.34 J2.16@-350,-1331.36 ; -318.29,-1363.07 J2.16@-350,-1331.36 ; -318.29,-1299.65 J2.16@-350,-1331.36 ; -307.98,-1331.36 J2.16@-350,-1331.36 ; -292.02,-1331.36 J2.14@-250,-1331.36 ; -281.71,-1363.07 J2.14@-250,-1331.36 ; -281.71,-1299.65 J2.14@-250,-1331.36 ; -250,-1373.38 J2.14@-250,-1331.36 ; -250,-1289.34 J2.14@-250,-1331.36 ; -218.29,-1363.07 J2.14@-250,-1331.36 ; -218.29,-1299.65 J2.14@-250,-1331.36 ; -207.98,-1331.36 J2.14@-250,-1331.36 ; -192.02,-1331.36 J2.12@-150,-1331.36 ; -181.71,-1363.07 J2.12@-150,-1331.36 ; -181.71,-1299.65 J2.12@-150,-1331.36 ; -150,-1373.38 J2.12@-150,-1331.36 ; -150,-1289.34 J2.12@-150,-1331.36 ; -118.29,-1363.07 J2.12@-150,-1331.36 ; -118.29,-1299.65 J2.12@-150,-1331.36 ; -107.98,-1331.36 J2.12@-150,-1331.36 ; 307.98,-1331.36 J2.2@350,-1331.36 ; 318.29,-1363.07 J2.2@350,-1331.36 ; 318.29,-1299.65 J2.2@350,-1331.36 ; 350,-1373.38 J2.2@350,-1331.36 ; 350,-1289.34 J2.2@350,-1331.36 ; 381.71,-1363.07 J2.2@350,-1331.36 ; 381.71,-1299.65 J2.2@350,-1331.36 ; 392.02,-1331.36 J2.2@350,-1331.36 ; 450.81,1550.79 UT13.88@492.83,1550.79 ; 461.12,1519.08 UT13.88@492.83,1550.79 ; 461.12,1582.5 UT13.88@492.83,1550.79 ; 492.83,1508.77 UT13.88@492.83,1550.79 ; 492.83,1592.81 UT13.88@492.83,1550.79 ; 524.54,1519.08 UT13.88@492.83,1550.79 ; 524.54,1582.5 UT13.88@492.83,1550.79 ; 534.85,1550.79 UT13.88@492.83,1550.79 ; 550.81,1550.79 UT13.86@592.83,1550.79 ; 561.12,1519.08 UT13.86@592.83,1550.79 ; 561.12,1582.5 UT13.86@592.83,1550.79 ; 592.83,1508.77 UT13.86@592.83,1550.79 ; 592.83,1592.81 UT13.86@592.83,1550.79 ; 624.54,1519.08 UT13.86@592.83,1550.79 ; 624.54,1582.5 UT13.86@592.83,1550.79 ; 634.85,1550.79 UT13.86@592.83,1550.79 ; 650.81,1550.79 UT13.84@692.83,1550.79 ; 661.12,1519.08 UT13.84@692.83,1550.79 ; 661.12,1582.5 UT13.84@692.83,1550.79 ; 692.83,1508.77 UT13.84@692.83,1550.79 ; 692.83,1592.81 UT13.84@692.83,1550.79 ; 724.54,1519.08 UT13.84@692.83,1550.79 ; 724.54,1582.5 UT13.84@692.83,1550.79 ; 734.85,1550.79 UT13.84@692.83,1550.79 ; 750.81,1550.79 UT13.82@792.83,1550.79 ; 761.12,1519.08 UT13.82@792.83,1550.79 ; 761.12,1582.5 UT13.82@792.83,1550.79 ; 792.83,1508.77 UT13.82@792.83,1550.79 ; 792.83,1592.81 UT13.82@792.83,1550.79 ; 824.54,1519.08 UT13.82@792.83,1550.79 ; 824.54,1582.5 UT13.82@792.83,1550.79 ; 834.85,1550.79 UT13.82@792.83,1550.79 ; 1687.98,1460 UT13.22@1730,1460 ; 1698.29,1428.29 UT13.22@1730,1460 ; 1698.29,1491.71 UT13.22@1730,1460 ; 1730,1417.98 UT13.22@1730,1460 ; 1730,1502.02 UT13.22@1730,1460 ; 1761.71,1428.29 UT13.22@1730,1460 ; 1761.71,1491.71 UT13.22@1730,1460 ; 1772.02,1460 UT13.22@1730,1460 ; 1787.98,-240 UT13.20@1830,-240 ; 1798.29,-271.71 UT13.20@1830,-240 ; 1798.29,-208.29 UT13.20@1830,-240 ; 1812.7,-1331.36 J3.16@1854.72,-1331.36 ; 1823.01,-1363.07 J3.16@1854.72,-1331.36 ; 1823.01,-1299.65 J3.16@1854.72,-1331.36 ; 1830,-282.02 UT13.20@1830,-240 ; 1830,-197.98 UT13.20@1830,-240 ; 1854.72,-1373.38 J3.16@1854.72,-1331.36 ; 1854.72,-1289.34 J3.16@1854.72,-1331.36 ; 1861.71,-271.71 UT13.20@1830,-240 ; 1861.71,-208.29 UT13.20@1830,-240 ; 1872.02,-240 UT13.20@1830,-240 ; 1886.43,-1363.07 J3.16@1854.72,-1331.36 ; 1886.43,-1299.65 J3.16@1854.72,-1331.36 ; 1896.74,-1331.36 J3.16@1854.72,-1331.36 ; 1912.7,-1331.36 J3.14@1954.72,-1331.36 ; 1923.01,-1363.07 J3.14@1954.72,-1331.36 ; 1923.01,-1299.65 J3.14@1954.72,-1331.36 ; 1954.72,-1373.38 J3.14@1954.72,-1331.36 ; 1954.72,-1289.34 J3.14@1954.72,-1331.36 ; 1986.43,-1363.07 J3.14@1954.72,-1331.36 ; 1986.43,-1299.65 J3.14@1954.72,-1331.36 ; 1996.74,-1331.36 J3.14@1954.72,-1331.36 ; 2012.7,-1331.36 J3.12@2054.72,-1331.36 ; 2023.01,-1363.07 J3.12@2054.72,-1331.36 ; 2023.01,-1299.65 J3.12@2054.72,-1331.36 ; 2054.72,-1373.38 J3.12@2054.72,-1331.36 ; 2054.72,-1289.34 J3.12@2054.72,-1331.36 ; 2086.43,-1363.07 J3.12@2054.72,-1331.36 ; 2086.43,-1299.65 J3.12@2054.72,-1331.36 ; 2096.74,-1331.36 J3.12@2054.72,-1331.36 ; 2512.7,-1331.36 J3.2@2554.72,-1331.36 ; 2523.01,-1363.07 J3.2@2554.72,-1331.36 ; 2523.01,-1299.65 J3.2@2554.72,-1331.36 ; 2554.72,-1373.38 J3.2@2554.72,-1331.36 ; 2554.72,-1289.34 J3.2@2554.72,-1331.36 ; 2586.43,-1363.07 J3.2@2554.72,-1331.36 ; 2586.43,-1299.65 J3.2@2554.72,-1331.36 ; 2596.74,-1331.36 J3.2@2554.72,-1331.36
  GND2 w20: -5063.02,-1860 J11.2@-5011,-1860 ; -5049.78,-1898.78 J11.2@-5011,-1860 ; -5049.78,-1821.22 J11.2@-5011,-1860 ; -5011,-1912.02 J11.2@-5011,-1860 ; -5011,-1807.98 J11.2@-5011,-1860 ; -4972.22,-1898.78 J11.2@-5011,-1860 ; -4972.22,-1821.22 J11.2@-5011,-1860 ; -4958.98,-1860 J11.2@-5011,-1860 ; -4945.02,-2045 J11.3@-4893,-2045 ; -4931.78,-2083.78 J11.3@-4893,-2045 ; -4931.78,-2006.22 J11.3@-4893,-2045 ; -4893,-2097.02 J11.3@-4893,-2045 ; -4893,-1992.98 J11.3@-4893,-2045 ; -4854.22,-2083.78 J11.3@-4893,-2045 ; -4854.22,-2006.22 J11.3@-4893,-2045 ; -4840.98,-2045 J11.3@-4893,-2045
  GND2 w22: -3632.02,-1855 J12.2@-3590,-1855 ; -3632.02,-1525 J13.2@-3590,-1525 ; -3621.71,-1886.71 J12.2@-3590,-1855 ; -3621.71,-1823.29 J12.2@-3590,-1855 ; -3621.71,-1556.71 J13.2@-3590,-1525 ; -3621.71,-1493.29 J13.2@-3590,-1525 ; -3590,-1897.02 J12.2@-3590,-1855 ; -3590,-1812.98 J12.2@-3590,-1855 ; -3590,-1567.02 J13.2@-3590,-1525 ; -3590,-1482.98 J13.2@-3590,-1525 ; -3558.29,-1886.71 J12.2@-3590,-1855 ; -3558.29,-1823.29 J12.2@-3590,-1855 ; -3558.29,-1556.71 J13.2@-3590,-1525 ; -3558.29,-1493.29 J13.2@-3590,-1525 ; -3547.98,-1855 J12.2@-3590,-1855 ; -3547.98,-1525 J13.2@-3590,-1525 ; -3186.86,-645 UT26.2@-3140.47,-645 ; -3175.27,-679.8 UT26.2@-3140.47,-645 ; -3175.27,-610.2 UT26.2@-3140.47,-645 ; -3105.67,-679.8 UT26.2@-3140.47,-645 ; -3105.67,-610.2 UT26.2@-3140.47,-645 ; -3094.08,-645 UT26.2@-3140.47,-645 ; -2486.86,-645 UT27.2@-2440.47,-645 ; -2475.27,-679.8 UT27.2@-2440.47,-645 ; -2475.27,-610.2 UT27.2@-2440.47,-645 ; -2405.67,-679.8 UT27.2@-2440.47,-645 ; -2405.67,-610.2 UT27.2@-2440.47,-645 ; -2394.08,-645 UT27.2@-2440.47,-645
  BOTTOM w15: v1(-150,-690) -145,-695 -35,-695 -8.5,-668.5 CB23.2@-8.5,-650 ; v1(-55,-415) -8.5,-461.5 CB21.2@-8.5,-470 ; v1(315,-560) 336.5,-581.5 CB22.2@336.5,-650 ; CB20.2@321.5,-405 336.5,-420 v1(365,-420)
  BOTTOM w20: CB12.2@-1570,1290.22 CB11.2@-1470,1290.22 v1(-1365.22,1290.22) CB10.2@-1270,1290.22 CB9.2@-1170,1290.22 ; CB19.2@-1501.5,100 v1(-1501.5,161.5) ; UB3.2@-1257.5,100 v1(-1217.5,100) ; CB8.2@-870,1290.22 -824.78,1290.22 -760,1355 -760,1450 UT13.62@-770,1460 ; v1(850,1350) 891.5,1308.5 CB7.2@930,1308.5 CB6.2@1030,1308.5 CB5.2@1130,1308.5
  BOTTOM w25: CB16.2@99.25,812.66 118.75,793.16 UB2.3@214.25,793.16 ; v1(214.25,739.16) UB2.3@214.25,793.16 ; CB18.2@327.75,754.16 329.25,755.66 CB15.2@329.25,812.66 267.75,812.66 249.25,794.16 215.25,794.16 UB2.3@214.25,793.16 ; CB4.2@1230,1312 CB3.2@1330,1312 CB2.2@1430,1312 CB1.2@1530,1312 1577,1312 v1(1610,1345) ; v1(1995,840.38) 2002.71,832.67 CB14.2@2049.25,832.67 2068.75,813.17 UB1.3@2164.25,813.17 2165.25,814.17 2199.25,814.17 2217.75,832.67 CB13.2@2279.25,832.67 2279.25,775.67 CB17.2@2277.75,774.17
  other v1: 3674.81,-1374.67 3674.81,-1344.67 3674.81,-1314.67 4889.43,-1312.9 4919.43,-1312.9 4635.16,-1289.63 4665.16,-1289.63 4695.16,-1289.63 4725.16,-1289.63 4332.43,-1288.9 4362.43,-1288.9 3614.81,-1284.67 3644.81,-1284.67 3674.81,-1284.67 4889.43,-1282.9 4919.43,-1282.9 4635.16,-1259.63 4665.16,-1259.63 4695.16,-1259.63 4725.16,-1259.63 4332.43,-1258.9 4362.43,-1258.9 4635.16,-1229.63 4665.16,-1229.63 4695.16,-1229.63 4725.16,-1229.63 4635.16,-1199.63 4665.16,-1199.63 4695.16,-1199.63 4725.16,-1199.63 3996.33,-1176.81 4026.33,-1176.81 4056.33,-1176.81 4086.33,-1176.81 4635.16,-1169.63 4665.16,-1169.63 4695.16,-1169.63 4725.16,-1169.63 3996.33,-1146.81 4026.33,-1146.81 4056.33,-1146.81 4086.33,-1146.81 3805.16,-1124.63 3835.16,-1124.63 3865.16,-1124.63 3895.16,-1124.63 3502.43,-1123.9 3532.43,-1123.9 3996.33,-1116.81 4026.33,-1116.81 4056.33,-1116.81 4086.33,-1116.81 3805.16,-1094.63 3835.16,-1094.63 3865.16,-1094.63 3895.16,-1094.63 3502.43,-1093.9 3532.43,-1093.9 3805.16,-1064.63 3835.16,-1064.63 3865.16,-1064.63 3895.16,-1064.63 3805.16,-1034.63 3835.16,-1034.63 3865.16,-1034.63 3895.16,-1034.63 3805.16,-1004.63 3835.16,-1004.63 3865.16,-1004.63 3895.16,-1004.63
1: CT37.2 CT47.2 J9.3 J9.5 J9.10 J9.11 UT11.5 UT17.4 | length 3597.3
  TOP w20: CT47.2@-4700,460.43 -4579.57,460.43 -4510,530 UT17.4@-4510,615 -4540,615 v1(-4578.5,653.5) -4635,653.5 CT37.2@-4665,683.5 ; v1(-4675,1045) UT11.5@-4552.5,1045
  GND1 w7: -4921.52,533 J9.5@-4885,533 ; -4921.52,749 J9.3@-4885,749 ; -4912.82,505.18 J9.5@-4885,533 ; -4912.82,560.82 J9.5@-4885,533 ; -4912.82,721.18 J9.3@-4885,749 ; -4912.82,776.82 J9.3@-4885,749 ; -4885,496.48 J9.5@-4885,533 ; -4885,569.52 J9.5@-4885,533 ; -4885,712.48 J9.3@-4885,749 ; -4885,785.52 J9.3@-4885,749 ; -4857.18,505.18 J9.5@-4885,533 ; -4857.18,560.82 J9.5@-4885,533 ; -4857.18,721.18 J9.3@-4885,749 ; -4857.18,776.82 J9.3@-4885,749 ; -4848.48,533 J9.5@-4885,533 ; -4848.48,749 J9.3@-4885,749
  GND1 w20: -5013.02,263 J9.11@-4939,263 ; -5013.02,1235 J9.10@-4939,1235 ; -4993.34,208.66 J9.11@-4939,263 ; -4993.34,317.34 J9.11@-4939,263 ; -4993.34,1180.66 J9.10@-4939,1235 ; -4993.34,1289.34 J9.10@-4939,1235 ; -4939,188.98 J9.11@-4939,263 ; -4939,337.02 J9.11@-4939,263 ; -4939,1160.98 J9.10@-4939,1235 ; -4939,1309.02 J9.10@-4939,1235 ; -4884.66,208.66 J9.11@-4939,263 ; -4884.66,317.34 J9.11@-4939,263 ; -4884.66,1180.66 J9.10@-4939,1235 ; -4884.66,1289.34 J9.10@-4939,1235 ; -4864.98,263 J9.11@-4939,263 ; -4864.98,1235 J9.10@-4939,1235
  GND2 w7: -4919.52,533 J9.5@-4885,533 ; -4919.52,749 J9.3@-4885,749 ; -4911.41,506.59 J9.5@-4885,533 ; -4911.41,559.41 J9.5@-4885,533 ; -4911.41,722.59 J9.3@-4885,749 ; -4911.41,775.41 J9.3@-4885,749 ; -4885,498.48 J9.5@-4885,533 ; -4885,567.52 J9.5@-4885,533 ; -4885,714.48 J9.3@-4885,749 ; -4885,783.52 J9.3@-4885,749 ; -4858.59,506.59 J9.5@-4885,533 ; -4858.59,559.41 J9.5@-4885,533 ; -4858.59,722.59 J9.3@-4885,749 ; -4858.59,775.41 J9.3@-4885,749 ; -4850.48,533 J9.5@-4885,533 ; -4850.48,749 J9.3@-4885,749
  GND2 w20: -4991.93,210.07 J9.11@-4939,263 ; -4991.93,315.93 J9.11@-4939,263 ; -4991.93,1182.07 J9.10@-4939,1235 ; -4991.93,1287.93 J9.10@-4939,1235 ; -4886.07,210.07 J9.11@-4939,263 ; -4886.07,315.93 J9.11@-4939,263 ; -4886.07,1182.07 J9.10@-4939,1235 ; -4886.07,1287.93 J9.10@-4939,1235
+1V5REF: CB13.1 RB19.1 RT29.1 RT75.1 RT93.1 UB1.2 | length 1311.6
  TOP w25: v1(2315.67,665.67) 2315.67,711.05 RT75.1@2316.5,711.88 ; v1(2315.67,1115.67) 2315.67,1170.11 RT29.1@2316.5,1170.94 ; v1(2316.5,201.5) RT93.1@2316.5,252.82
  BOTTOM w25: UB1.2@2201.25,892.17 2275.75,892.17 CB13.1@2279.25,895.67 RB19.1@2339.25,895.67 ; v1(2316.5,201.5) 2316.5,664.84 v1(2315.67,665.67) 2360.67,665.67 2390,695 2390,870.67 2365,895.67 RB19.1@2339.25,895.67 ; v1@2316.5,1116.5 v1(2315.67,1115.67) 2339.25,1092.09 RB19.1@2339.25,895.67
+3V3: CB14.1 CB16.1 CB19.1 CT1.1 CT4.1 CT7.1 CT8.1 CT9.1 CT10.1 CT11.1 CT12.1 CT13.1 CT30.1 CT35.1 CT39.1 CT44.1 CT45.1 CT46.1 CT48.1 CT49.1 CT50.1 CT60.1 CT61.1 CT62.1 J10.10 RT69.1 RT70.1 RT71.1 RT83.2 RT100.1 RT106.1 RT110.1 RT112.1 RT120.1 UB1.1 UB2.1 UB3.5 UT1.5 UT2.5 UT3.5 UT4.5 UT5.5 UT6.5 UT7.5 UT8.5 UT9.5 UT10.5 UT11.1 UT12.5 UT13.1 UT13.41 UT13.102 UT14.3 UT14.8 UT15.3 UT15.8 UT16.3 UT16.8 UT18.5 UT19.16 UT20.16 UT24.16 UT25.16 UT27.3 | length 5509.8
  TOP w10: -1286,626 UT14.8@-1265,626 ; v1(-1230,540) -1225,535 UT14.3@-1225,504 ; -1026,626 UT15.8@-1005,626 ; v1(-970,540) -965,535 UT15.3@-965,504 ; -766,626 UT16.8@-745,626 ; v1(-710,540) -705,535 UT16.3@-705,504 ; v1(1750,-795) 1765,-810 RT120.1@1803.5,-810
  TOP w15: CT44.1@-1325,596.5 -1325,625 v1(-1305,645) ; -1286,626 v1(-1305,645) ; RT69.1@-1193.5,740 -1193.5,758.5 -1215,780 -1280,780 -1305,755 v1(-1305,645) ; v1(-1080,205) RT100.1@-1041.5,205 ; CT45.1@-1065,596.5 -1065,625 v1(-1045,645) ; -1026,626 v1(-1045,645) ; RT70.1@-933.5,740 -933.5,758.5 -955,780 -1020,780 -1045,755 v1(-1045,645) ; CT46.1@-805,596.5 -805,625 v1(-785,645) ; -766,626 v1(-785,645) ; v1(-710,335) -706.5,338.5 CT50.1@-670,338.5 -677.8,330.7 UT19.16@-677.8,284.57 ; RT71.1@-673.5,740 -673.5,758.5 -695,780 -760,780 -785,755 v1(-785,645) ; v1(-350,-580.33) -350,-560 -335,-545 RT112.1@-321.5,-545 ; v1(-270,277.2) UT20.16@-234.57,277.2 -234.57,353.07 CT49.1@-235,353.5 ; RT83.2@-180.63,655 v1(-130,655) ; v1(-160,-135) RT106.1@-160,-92.78 ; UT24.16@57.2,-470.43 57.2,-419.3 CT60.1@61.5,-415 v1(105,-415) ; v1(1671.5,-466.5) CT61.1@1720,-466.5 1754.19,-466.5 1755.49,-467.8 UT25.16@1780.43,-467.8
  TOP w20: UT11.1@-4177.5,745 -4068.5,745 CT39.1@-4065,741.5 v1(-4016.5,741.5) ; v1(-1470.1,818.24) UT10.5@-1470.1,862.49 -1463.81,856.2 CT30.1@-1409.53,856.2 ; CT7.1@-1161.65,1152.4 -1148.15,1152.4 -1126.99,1131.24 v1(-1126.99,1122.4) -1126.99,1102.81 UT3.5@-1140,1089.8 ; CT8.1@-902.47,1152.4 -888.97,1152.4 -867.81,1131.24 v1(-867.81,1122.4) -867.81,1102.81 UT4.5@-880.82,1089.8 ; CT9.1@-643.29,1152.4 -629.79,1152.4 -608.63,1131.24 v1(-608.63,1122.4) -608.63,1102.81 UT5.5@-621.64,1089.8 ; CT10.1@-384.11,1152.4 -370.61,1152.4 -349.45,1131.24 v1(-349.45,1122.4) -349.45,1102.81 UT6.5@-362.46,1089.8 ; CT11.1@711.94,1115.66 711.94,1061.38 UT7.5@705.65,1055.09 v1(749.9,1055.09) ; CT12.1@1050.46,1115.66 1050.46,1061.38 UT8.5@1044.17,1055.09 v1(1088.42,1055.09) ; CT13.1@1388.98,1115.66 1388.98,1061.38 UT9.5@1382.69,1055.09 v1(1426.94,1055.09) ; CT48.1@2045,444.32 2104.25,444.32 UT18.5@2107.6,440.97 v1(2107.6,485.22) ; CT35.1@2045,903.38 2104.25,903.38 UT12.5@2107.6,900.03 v1(2107.6,944.28) ; CT4.1@2045,1362.44 2104.25,1362.44 UT2.5@2107.6,1359.09 v1(2107.6,1403.34) ; CT1.1@2045,1821.5 2104.25,1821.5 UT1.5@2107.6,1818.15 v1(2107.6,1862.4)
  TOP w25: UT27.3@-2440.47,-545 -2351.63,-545 -2347.06,-549.57 CT62.1@-2300,-549.57 -2300,-386.43 -2290.63,-377.06 RT110.1@-2290.63,-330
  PWR w7: -4916.86,-911.86 J10.10@-4900,-895 ; -4916.86,-878.14 J10.10@-4900,-895 ; -4883.14,-911.86 J10.10@-4900,-895 ; -4883.14,-878.14 J10.10@-4900,-895 ; -2012.02,-240 UT13.102@-1970,-240 ; -2001.71,-271.71 UT13.102@-1970,-240 ; -2001.71,-208.29 UT13.102@-1970,-240 ; -1970,-282.02 UT13.102@-1970,-240 ; -1970,-197.98 UT13.102@-1970,-240 ; -1938.29,-271.71 UT13.102@-1970,-240 ; -1938.29,-208.29 UT13.102@-1970,-240 ; -1927.98,-240 UT13.102@-1970,-240 ; -712.02,1560 UT13.41@-670,1560 ; -701.71,1528.29 UT13.41@-670,1560 ; -701.71,1591.71 UT13.41@-670,1560 ; -670,1517.98 UT13.41@-670,1560 ; -670,1602.02 UT13.41@-670,1560 ; -638.29,1528.29 UT13.41@-670,1560 ; -638.29,1591.71 UT13.41@-670,1560 ; -627.98,1560 UT13.41@-670,1560 ; 1787.98,1560 UT13.1@1830,1560 ; 1798.29,1528.29 UT13.1@1830,1560 ; 1798.29,1591.71 UT13.1@1830,1560 ; 1830,1517.98 UT13.1@1830,1560 ; 1830,1602.02 UT13.1@1830,1560 ; 1861.71,1528.29 UT13.1@1830,1560 ; 1861.71,1591.71 UT13.1@1830,1560 ; 1872.02,1560 UT13.1@1830,1560
  PWR w22: -2486.86,-545 UT27.3@-2440.47,-545 ; -2475.27,-579.8 UT27.3@-2440.47,-545 ; -2475.27,-510.2 UT27.3@-2440.47,-545 ; -2440.47,-498.61 UT27.3@-2440.47,-545 ; -2405.67,-579.8 UT27.3@-2440.47,-545 ; -2405.67,-510.2 UT27.3@-2440.47,-545 ; -2394.08,-545 UT27.3@-2440.47,-545
  BOTTOM w20: v1(-1438.5,158.5) CB19.1@-1438.5,100 UB3.5@-1363.5,100 ; CB14.1@2049.25,895.67 2049.25,914.53 2079,944.28 v1(2107.6,944.28) 2127.25,924.63 UB1.1@2127.25,892.17
  BOTTOM w25: v1(50.66,875.66) CB16.1@99.25,875.66 173.75,875.66 UB2.1@177.25,872.16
